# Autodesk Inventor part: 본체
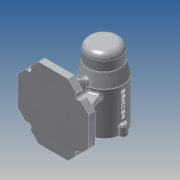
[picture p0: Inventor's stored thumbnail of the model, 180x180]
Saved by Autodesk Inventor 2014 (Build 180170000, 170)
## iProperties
Created: 2019-12
Part Number: 본체
Material: 알루미늄 6061
Document SubType Name: Modeling
Designer: kb542-15
Density: 2.71 g/cm^3
Appearance: 알루미늄 - 평지
Mass: 728.494 g
Surface Area: 714.691 cm^2
Volume: 268.817 cm^3
Author: kb542-15
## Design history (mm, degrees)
sketch "스케치1"
  geometry: L1 (0, 0)-(36, 0); L2 (0, 0)-(-36, 0); L3 (-36, 0)-(-10.522, 70); L4 (-36, 0)-(59.856, 0); L5 (36, 0)-(10.522, 70); L6 (36, 0)-(130.15, 0); L7 (0, 70)-(10.522, 70); L8 (10.522, 70)-(-10.522, 70)
  constraints: 16 end point, 3 horizontal, 2 collinear
  dimensions: "d0" = 36 distance of L1.start L1.end; "d1" = 36 distance of L1.start L2.end; "d2" = 70 deg angle of L4 L3; "d3" = 110 deg angle of L6 L5
extrude "돌출1" new body sketch "스케치1" stored distance "d5" = 8; taper "d6" = 0 deg
sketch "스케치2"
  geometry: L1 (0, 0)-(0, 38); L2 (0, 38)-(70, 5.358); L3 (0, 0)-(0, -31); L4 (0, -31)-(70, -31); L5 (70, -31)-(70, 5.358)
  constraints: 10 end point, 1 collinear, 1 perpendicular, 1 vertical
  dimensions: "d7" = 38 distance of L1.start L1.end; "d8" = 65 deg angle of L1 L2; "d9" = 31 distance of L1.start L3.end; "d10" = 70 distance of L3.end L4.end
extrude "돌출2" join sketch "스케치2" stored distance "d11" = 8; taper "d12" = 0 deg
sketch "스케치3"
  geometry: L1 (20, -19.196)-(-12.804, -52); L2 (-12.804, -52)-(-59.196, -52); L3 (-59.196, -52)-(-92, -19.196); L4 (-92, -19.196)-(-92, 27.196); L5 (-92, 27.196)-(-59.196, 60); L6 (-59.196, 60)-(-12.804, 60); L7 (-12.804, 60)-(20, 27.196); L8 (20, 27.196)-(20, -19.196); 4 further points
  constraints: 16 end point, 1 coincident, 1 horizontal alignment, 1 midpoint, 19 other
extrude "돌출3" join sketch "스케치3" distance "d14" = 10; taper "d15" = 0 deg
revolve "회전1" stored, may be unused: angle "d27" = 90 deg
sketch "스케치5"
  geometry: C1 r 6 at (0, 30); C2 r 6 at (30, 0); C3 r 6 at (0, -30); C4 r 6 at (-30, 0); A1 r 30 centre (0, 0) between (0, 30) and (30, 0) reference; 1 further point
  constraints: 4 centre point, 4 point on circle
  dimensions: "d28" = 12 diameter of C1; "d29" = 12 diameter of C2; "d30" = 12 diameter of C3; "d31" = 12 diameter of C4
extrude "돌출4" join sketch "스케치5" distance "d32" = 16; taper "d33" = 0 deg
sketch "스케치6"
  geometry: C1 r 21 at (0, 30); A1 r 30 centre (0, 30) between (-5.97, 59.4) and (-29.4, 35.97) reference; 1 further point
  constraints: 1 centre point, 1 coincident
  dimensions: "d34" = 42 diameter of C1
extrude "돌출5" cut sketch "스케치6" distance "d35" = 15; taper "d36" = 0 deg
sketch "스케치7"
  geometry: C1 r 21 at (0, 0) reference; C2 r 24 at (0, 0); 1 further point
  constraints: 1 centre point, 1 coincident
  dimensions: "d37" = 48 diameter of C2
extrude "돌출6" cut sketch "스케치7" distance "d38" = 54; taper "d39" = 0 deg
sketch "스케치8"
  geometry: C1 r 24 at (0, 0) reference; C2 r 21 at (0, 0); 1 further point
  constraints: 1 centre point, 1 coincident
  dimensions: "d40" = 42 diameter of C2
extrude "돌출7" cut sketch "스케치8" distance "d41" = 12; taper "d42" = 0 deg
sketch "스케치9"
  geometry: C1 r 21 at (0, 0) reference; C2 r 17.5 at (0, 0); 1 further point
  constraints: 1 centre point, 1 coincident
  dimensions: "d43" = 35 diameter of C2
extrude "돌출8" cut sketch "스케치9" distance "d44" = 18; taper "d45" = 0 deg
sketch "스케치10"
  geometry: C1 r 17.5 at (0, 0) reference; C2 r 16 at (0, 0); 1 further point
  constraints: 1 centre point, 1 coincident
  dimensions: "d46" = 32 diameter of C2
extrude "돌출9" cut sketch "스케치10" distance "d47" = 4; taper "d48" = 0 deg
sketch "스케치11"
  geometry: C1 r 16 at (0, 0) reference; C2 r 10.5 at (0, 0); 1 further point
  constraints: 1 centre point, 1 coincident
  dimensions: "d49" = 21 diameter of C2
extrude "돌출10" cut sketch "스케치11" distance "d50" = 3; taper "d51" = 0 deg
sketch "스케치12"
  geometry: L1 (-36, -4)-(20, -4); 4 further points
  constraints: 2 end point, 1 horizontal
hole "구멍1" sketch "스케치12" at (-75.598, 35.598), (-75.598, -43.598), (3.598, -43.598), (3.598, 35.598) diameter "d53" = 10; stored, may be unused: countersink angle "d57" = 90 deg, drill point angle "d59" = 118 deg; dims "d54" = 6, "d55" = 4, "d56" = 2, "d58" = 8
sketch "스케치13"
  geometry: A1 r 6 centre (0, 0) between (-5.97, 0.6) and (5.97, 0.6) reference; A2 r 6 centre (30, 30) between (29.4, 24.03) and (29.4, 35.97) reference; A3 r 6 centre (0, 60) between (5.97, 59.4) and (-5.97, 59.4) reference; A4 r 6 centre (-30, 30) between (-29.4, 35.97) and (-29.4, 24.03) reference; 5 further points
  constraints: 4 coincident
hole "구멍2" sketch "스케치13" at (0, 60), (30, 30), (0, 0), (-30, 30) diameter "d60" = 3.242; stored, may be unused: countersink angle "d64" = 90 deg, drill point angle "d66" = 118 deg; dims "d61" = 8, "d62" = 4, "d63" = 2, "d65" = 11
fillet "모깎기1" dims "d67" = 0.3
fillet "모깎기2" dims "d68" = 3
fillet "모깎기3" dims "d69" = 3
chamfer "모따기1" distance "d70" = 1; stored, may be unused: second distance "d71" = 2, angle "d72" = 45 deg
fillet "모깎기4" dims "d73" = 10
fillet "모깎기5" dims "d74" = 3
fillet "모깎기6" dims "d75" = 3
fillet "모깎기8" dims "d77" = 3
fillet "모깎기9" dims "d78" = 3
fillet "모깎기10" dims "d79" = 1
fillet "모깎기11" dims "d80" = 3
fillet "모깎기12" dims "d81" = 3
node "작업 평면1"
sketch "스케치14"
  geometry: L1 (73.002, 5.739)-(73.002, -35.739); L2 (73.002, -35.739)-(66.998, -35.739); L3 (66.998, -35.739)-(66.998, 5.739); L4 (66.998, 5.739)-(73.002, 5.739); L5 (0, -56)-(-10, -56) reference; 1 further point
  constraints: 2 other
feature "엠보싱1" sketch "스케치14" dims "d0" = 36, "d1" = 36, "d2" = 70 deg, "d3" = 110 deg, "d87" = 0.5, "d88" = 0
node "솔리드1"
sketch "스케치4"
  geometry: L1 (-10, 0)-(70, 0); L2 (70, 0)-(70, -56); L3 (70, 0)-(70, 56); L4 (70, 56)-(95, 56); L5 (95, 56)-(95, 31); L6 (100, 11)-(95, 31); L7 (70, -56)-(100, -56); L8 (100, -56)-(100, 11); 1 further point
  constraints: 16 end point, 4 perpendicular, 1 collinear
  dimensions: "d22" = 25 distance of L3.end L4.end; "d23" = 25 distance of L4.end L5.end; "d26" = 30 distance of L2.end L7.end
other parameters: "d82" = 30.5
